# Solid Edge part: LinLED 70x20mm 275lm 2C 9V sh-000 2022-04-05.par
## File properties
Author: robert.pupel
Template: iso metric part.par
Last saved by: robert.pupel
Revision: 5
Application: Solid Edge
Gęstość: 0.000 kg/m^3
Dokładność: 0.990
Username: robert.pupel
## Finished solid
Body 1: solid body, 650 faces, 1660 edges, 1040 vertices.
  Faces by surface: plane 350, cylinder 140, spline 96, cone 30, sphere 16, torus 10, spun 8
  Edges by curve: line 1024, curve on surface 324, circle 192, ellipse 66, spline 50, intersection 4
Bounding box of the edges (mm; curved faces can reach further): 20.000 x 4.450 x 69.600, from (-10, -3.45, -34.8) to (10, 1, 34.8).
Cylindrical faces by radius (mm): R0.2 x46, R0.2169 x6, R0.25 x16, R0.3373 x6, R0.4 x8, R0.4006 x2, R0.4008 x2, R0.525 x2, R0.6 x20, R1 x16, R1.1 x4, R1.2 x10, R2.15 x2
Conical faces (half-angle, radius in mm at the cone's reference point): 0.5 deg R0.5056 x4, 0.5 deg R1.0082 x4, 1 deg R0.5511 x2, 10 deg R0.2132 x4, 10 deg R0.4132 x4, 18.8604 deg R1.0669 x4, 27.363 deg R0.6214 x2, 45 deg R0.575 x2, 45 deg R0.625 x4
Toroidal faces (ring radius, tube radius in mm): R0.8 r0.2 x4, R0.8522 r0.3 x2, R0.9002 r0.2 x2, R0.9018 r0.2 x2
Spherical faces by radius (mm): R0.2 x12, R0.6 x4
Planar faces by outward normal: +x 38, +y 9, +z 36, -x 38, -y 52, -z 36, oblique 141
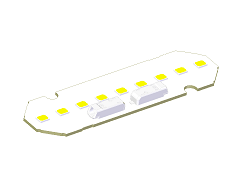
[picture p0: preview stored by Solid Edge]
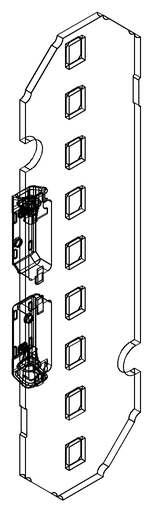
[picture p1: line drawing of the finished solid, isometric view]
